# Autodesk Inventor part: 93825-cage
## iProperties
Author: Administrator
Shininess: 64.0
Angle Display Precision: 2
Document Length Units: 11272
Document Angle Units: 11286
Document Time Units: 11279
Document Mass Units: 11290
Document Length Units Precision: 3
Document Angle Units Precision: 2
Compacted: True
PropertySet Name: _Private Model Information
Created: 2002-03
Part Number: 93825-cage
Material: Stainless Steel, 440C
Document SubType Name: Modeling
Designer: Administrator
Control State: 0
Master: False
Checked Out: False
PropertySet Name: Design Tracking Control
Density: 0.0
Volumn: 0.0
Area: 0.0
PropertySet Name: Model Information
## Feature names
1. Revolution1
2. Extrusion1
3. Circular Pattern1
